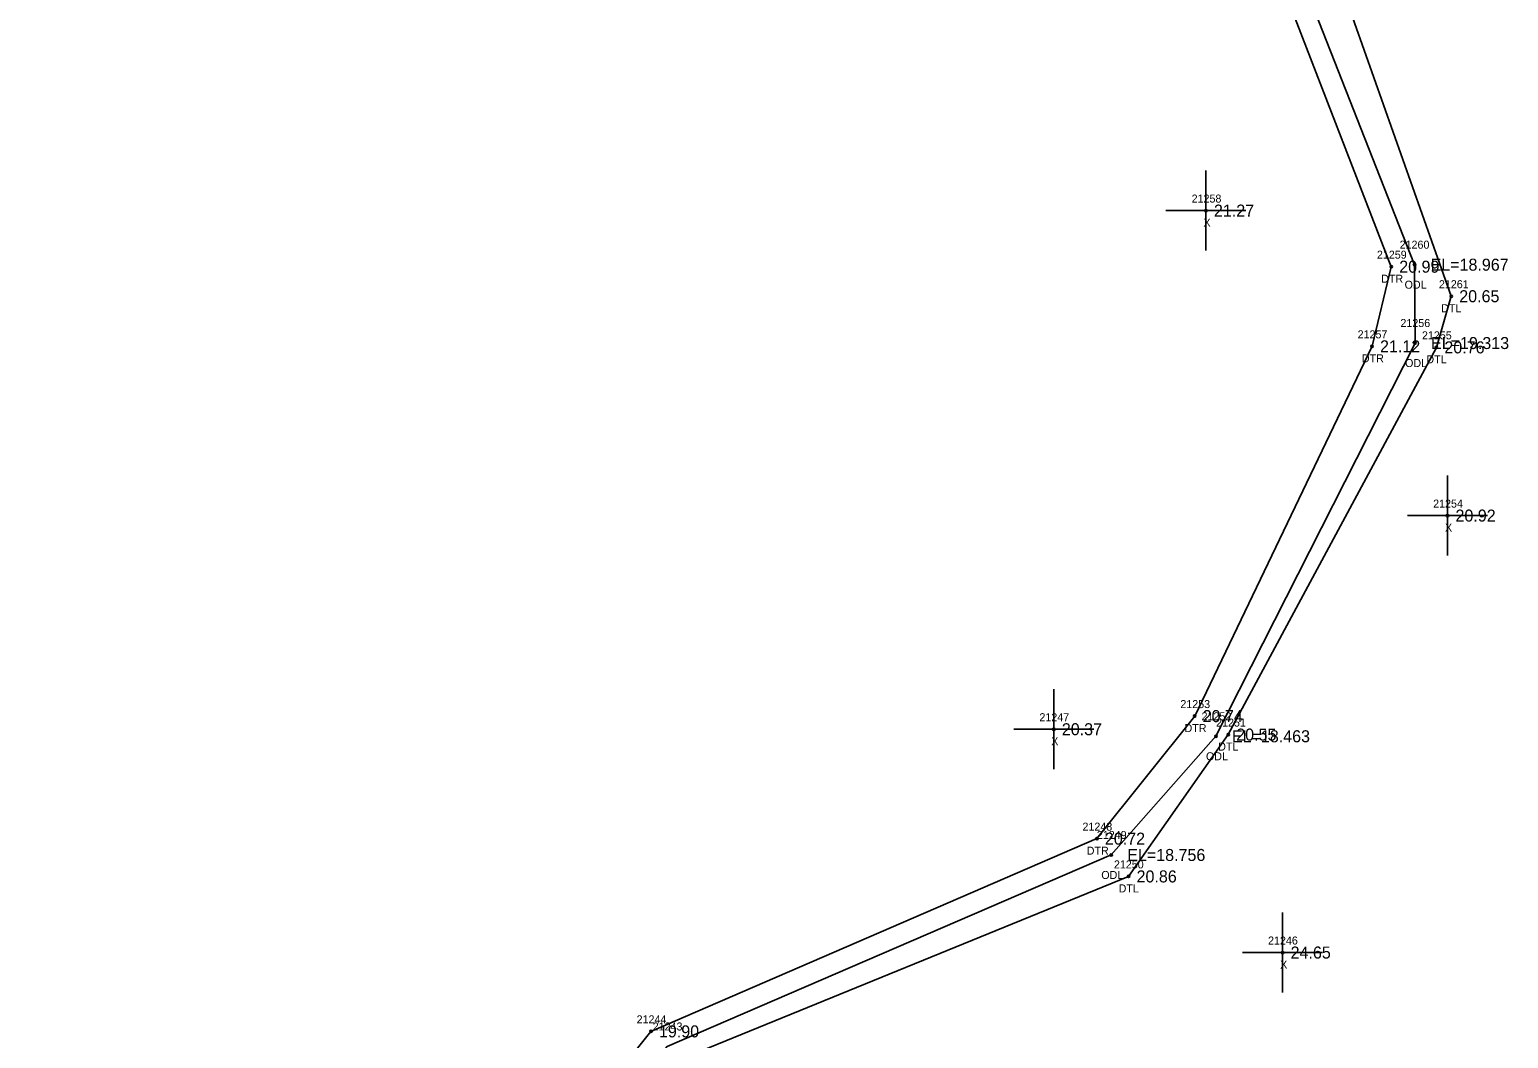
# Model space of a CAD drawing. Extents: x 2655177 to 2656219, y 761780 to 764748.
# Drawn here: x 2655506.1 to 2655690.9, y 762053.8 to 762179.8 of the extents above; entities that cross this region are included whole.
import ezdxf

# ---------------------------------------------------------------- set-up
doc = ezdxf.new("R2010")
doc.units = 0
for name, color, linetype in [('RD_EX_H2O', 7, 'Continuous'), ('RD_EX_H2O_txCode', 7, 'Continuous'), ('RD_EX_Misc', 7, 'Continuous'), ('RD_EX_Misc_txCode', 7, 'Continuous'), ('RD_EX_TX_H2O_ELEV', 7, 'Continuous'), ('RD_EX_TX_Misc_ELEV', 7, 'Continuous'), ('RD_SMD_Locator', 7, 'Continuous')]:
    doc.layers.add(name, color=color, linetype=linetype)

msp = doc.modelspace()

# ---------------------------------------------------------------- linework, layer by layer
at = {"layer": 'RD_EX_H2O'}
for points in [[(2655458.25, 762004.65), (2655489.16, 762003.6), (2655538.42, 762005.59), (2655556.05, 762013.17), (2655587.88, 762051.39), (2655643.4, 762074.04), (2655655.85, 762091.76), (2655681.86, 762140.14), (2655683.72, 762146.53), (2655664.39, 762201.23), (2655621.98, 762271.36), (2655558.86, 762321.08)], [(2655459.71, 762010.57), (2655488.92, 762008.22), (2655537.08, 762011.25), (2655554.9, 762018.55), (2655583.72, 762054.68), (2655639.44, 762078.76), (2655651.66, 762094.07), (2655673.82, 762140.27), (2655676.22, 762150.22), (2655658.16, 762196.88), (2655618.83, 762267.48), (2655556.47, 762317.07), (2655558.86, 762321.08)], [(2655456.91, 762008.75), (2655489.44, 762005.64), (2655537.92, 762008.34), (2655555.32, 762016.59), (2655585.73, 762052.79), (2655641.23, 762076.72), (2655654.31, 762091.55), (2655679.19, 762140.68), (2655679.13, 762150.47), (2655660.06, 762199), (2655620.4, 762269.42), (2655559.84, 762317.9)]]:
    msp.add_lwpolyline(points, dxfattribs=at)
at = {"layer": 'RD_EX_Misc'}
for p, q in [((2655653.07, 762152.23), (2655653.07, 762162.23)), ((2655648.07, 762157.23), (2655658.07, 762157.23)), ((2655683.25, 762114.12), (2655683.25, 762124.12)), ((2655678.25, 762119.12), (2655688.25, 762119.12)), ((2655634.06, 762087.43), (2655634.06, 762097.43)), ((2655629.06, 762092.43), (2655639.06, 762092.43)), ((2655662.65, 762059.53), (2655662.65, 762069.53)), ((2655657.65, 762064.53), (2655667.65, 762064.53))]:
    msp.add_line(p, q, dxfattribs=at)
at = {"layer": 'RD_SMD_Locator'}
for centre in [(2655653.07, 762157.23), (2655676.22, 762150.22), (2655679.13, 762150.47), (2655683.72, 762146.53), (2655679.19, 762140.68), (2655673.82, 762140.27), (2655681.86, 762140.14), (2655683.25, 762119.12), (2655651.66, 762094.07), (2655634.06, 762092.43), (2655654.31, 762091.55), (2655655.85, 762091.76), (2655639.44, 762078.76), (2655641.23, 762076.72), (2655643.4, 762074.04), (2655662.65, 762064.53), (2655583.72, 762054.68)]:
    msp.add_circle(centre, 0.15, dxfattribs=at)

# ---------------------------------------------------------------- texts
at = {"layer": 'RD_EX_H2O_txCode'}
for s, p in [('21259', (2655674.43, 762151.22)), ('21260', (2655677.27, 762152.47)), ('DTR', (2655674.96, 762148.22)), ('ODL', (2655677.89, 762147.47)), ('21261', (2655682.18, 762147.53)), ('DTL', (2655682.47, 762144.53)), ('21256', (2655677.37, 762142.68)), ('21257', (2655672.02, 762141.27)), ('21255', (2655680.06, 762141.14)), ('DTR', (2655672.55, 762138.27)), ('DTL', (2655680.61, 762138.14)), ('ODL', (2655677.95, 762137.68)), ('21253', (2655649.87, 762095.07)), ('21252', (2655652.52, 762093.55)), ('DTR', (2655650.39, 762092.07)), ('21251', (2655654.34, 762092.76)), ('ODL', (2655653.07, 762088.55)), ('DTL', (2655654.6, 762089.76)), ('21248', (2655637.64, 762079.76)), ('21249', (2655639.44, 762078.72)), ('DTR', (2655638.17, 762076.76)), ('21250', (2655641.57, 762075.04)), ('ODL', (2655639.99, 762073.72)), ('DTL', (2655642.16, 762072.04)), ('21244', (2655581.93, 762055.68)), ('21243', (2655583.94, 762054.79))]:
    msp.add_text(s, height=1, dxfattribs=at).set_placement(p)
at = {"layer": 'RD_EX_Misc_txCode'}
for s, p in [('21258', (2655651.28, 762158.23)), ('X', (2655652.76, 762155.23)), ('21254', (2655681.46, 762120.12)), ('X', (2655682.94, 762117.12)), ('21247', (2655632.26, 762093.43)), ('X', (2655633.74, 762090.43)), ('21246', (2655660.83, 762065.53)), ('X', (2655662.34, 762062.53))]:
    msp.add_text(s, height=1, dxfattribs=at).set_placement(p)
at = {"layer": 'RD_EX_TX_H2O_ELEV'}
for s, p in [('20.99', (2655677.22, 762149.47)), ('EL=18.967', (2655681.13, 762149.72)), ('20.65', (2655684.72, 762145.78)), ('21.12', (2655674.82, 762139.52)), ('EL=19.313', (2655681.19, 762139.93)), ('20.76', (2655682.86, 762139.39)), ('20.74', (2655652.66, 762093.32)), ('EL=18.463', (2655656.31, 762090.8)), ('20.55', (2655656.85, 762091.01)), ('20.72', (2655640.44, 762078.01)), ('EL=18.756', (2655643.23, 762075.97)), ('20.86', (2655644.4, 762073.29)), ('19.90', (2655584.72, 762053.93))]:
    msp.add_text(s, height=1.5, dxfattribs=at).set_placement(p)
at = {"layer": 'RD_EX_TX_Misc_ELEV'}
for s, p in [('21.27', (2655654.07, 762156.48)), ('20.92', (2655684.25, 762118.37)), ('20.37', (2655635.06, 762091.68)), ('24.65', (2655663.65, 762063.78))]:
    msp.add_text(s, height=1.5, dxfattribs=at).set_placement(p)

doc.saveas('drawing.dxf')
